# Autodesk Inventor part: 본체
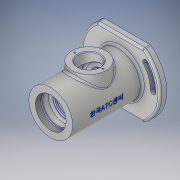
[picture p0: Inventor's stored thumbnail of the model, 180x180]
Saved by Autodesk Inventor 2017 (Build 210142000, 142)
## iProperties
Part Number: 본체
Material: 알루미늄 6061
Document SubType Name: Modeling
Designer: Administrator
Density: 2.7 g/cm^3
Appearance: 알루미늄 - 평지
Mass: 686.655 g
Surface Area: 618.901 cm^2
Volume: 254.317 cm^3
Author: Administrator
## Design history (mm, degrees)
sketch "스케치1"
  geometry: L1 (-33.985, 47)-(33.985, 47); L2 (33.985, 47)-(33.985, -47); L3 (33.985, -47)-(-33.985, -47); L4 (-33.985, -47)-(-33.985, 47); L5 (-33.985, 47)-(33.985, -47); L6 (33.985, 47)-(-33.985, -47); A1 r 58 centre (0, 0) between (-33.985, 47) and (-33.985, -47); A2 r 58 centre (0, 0) between (33.985, 47) and (-33.985, 47); A3 r 58 centre (0, 0) between (-33.985, -47) and (33.985, 47); 1 further point
  constraints: 12 end point, 8 point on circle, 3 centre point, 2 midpoint, 2 parallel, 1 coincident, 1 horizontal, 1 perpendicular
  dimensions: "d0" = 116 diameter of A1; "d1" = 94 distance of L3.end L1.start
extrude "돌출1" new body sketch "스케치1" distance "d2" = 10; taper "d3" = 0 deg
sketch "스케치2"
  geometry: C1 r 36 at (0, 0); 1 further point
  constraints: 1 centre point, 1 coincident
  dimensions: "d4" = 72 diameter of C1
extrude "돌출2" join sketch "스케치2" distance "d5" = 3; taper "d6" = 0 deg
sketch "스케치3"
  geometry: C1 r 32 at (0, 0); 1 further point
  constraints: 1 centre point, 1 coincident
  dimensions: "d7" = 64 diameter of C1
extrude "돌출3" join sketch "스케치3" distance "d8" = 102; taper "d9" = 0 deg
sketch "스케치4"
  geometry: L1 (0, 0)-(48, 0); L2 (0, 0)-(36.77, 30.854); L3 (-48, 0)-(0, 0); L4 (-36.77, -30.854)-(0, 0); C1 r 4 at (-36.77, -30.854); C2 r 4 at (36.77, 30.854); A1 r 48 centre (0, 0) between (48, 0) and (36.77, 30.854); A2 r 48 centre (0, 0) between (48, 0) and (36.77, 30.854); A3 r 48 centre (0, 0) between (-48, 0) and (-36.77, -30.854); 1 further point
  constraints: 8 end point, 8 point on circle, 5 centre point, 3 coincident, 2 concentric, 2 horizontal alignment
  dimensions: "d10" = 96 diameter of A1; "d11" = 40 deg angle of L1 L2; "d13" = 40 deg angle of L4 L3; "d15" = 8 diameter of C1; "d16" = 8 diameter of C2
extrude "돌출4" cut sketch "스케치4" distance "d17" = 10; taper "d18" = 0 deg
sketch "스케치5"
  geometry: L1 (-48, 0)-(48, 0); L2 (-36.77, -30.854)-(36.77, 30.854); C1 r 4 at (-36.77, -30.854) reference; C2 r 4 at (36.77, 30.854) reference; A1 r 48 centre (0, 0) between (-48, 0) and (48, 0); A2 r 48 centre (0, 0) between (48, 0) and (36.77, 30.854); A3 r 52 centre (0, 0) between (52, 0) and (39.834, 33.425); A4 r 44 centre (0, 0) between (44, 0) and (33.706, 28.283); A5 r 4 centre (48, 0) between (44, 0) and (52, 0); A6 r 4 centre (36.77, 30.854) between (39.834, 33.425) and (33.706, 28.283); A7 r 48 centre (0, 0) between (-48, 0) and (-36.77, -30.854); A8 r 52 centre (0, 0) between (-52, 0) and (-39.834, -33.425); A9 r 44 centre (0, 0) between (-44, 0) and (-33.706, -28.283); A10 r 4 centre (-48, 0) between (-44, 0) and (-52, 0); A11 r 4 centre (-36.77, -30.854) between (-39.834, -33.425) and (-33.706, -28.283); 2 further points
  constraints: 22 point on circle, 11 centre point, 8 tangent, 4 end point, 2 concentric, 2 horizontal alignment, 1 coincident, 1 horizontal, 1 midpoint
  dimensions: "d19" = 96 diameter of A1; "d20" = 8 diameter of A5; "d21" = 8 diameter of A10; "d22" = 30.85381 vertical distance of L2.start L1.start
extrude "돌출5" cut sketch "스케치5" distance "d23" = 4.4; taper "d24" = 0 deg
sketch "스케치6" dims "d25" = 96
  geometry: L1 (-36.77, -30.854)-(0, 0); L2 (0, 0)-(36.77, 30.854); L3 (0, 0)-(-48, 0); L4 (0, 0)-(48, 0); C1 r 4 at (-36.77, -30.854) reference; C2 r 4 at (36.77, 30.854) reference; A1 r 4 centre (48, 0) between (44, 0) and (52, 0) reference; A2 r 48 centre (0, 0) between (-48, 0) and (-36.77, -30.854); A3 r 50.25 centre (0, 0) between (-50.25, 0) and (-38.494, -32.3); A4 r 45.75 centre (0, 0) between (-45.75, 0) and (-35.047, -29.408); A5 r 2.25 centre (-48, 0) between (-45.75, 0) and (-50.25, 0); A6 r 2.25 centre (-36.77, -30.854) between (-38.494, -32.3) and (-35.047, -29.408); A7 r 48 centre (0, 0) between (48, 0) and (36.77, 30.854); A8 r 50.25 centre (0, 0) between (50.25, 0) and (38.494, 32.3); A9 r 45.75 centre (0, 0) between (45.75, 0) and (35.047, 29.408); A10 r 2.25 centre (48, 0) between (45.75, 0) and (50.25, 0); A11 r 2.25 centre (36.77, 30.854) between (38.494, 32.3) and (35.047, 29.408); 1 further point
  constraints: 20 point on circle, 10 centre point, 8 end point, 8 tangent, 2 horizontal, 1 coincident, 1 collinear, 1 concentric, 1 horizontal alignment, 3 other
  dimensions: "d26" = 4.5 diameter of A5; "d27" = 4.5 diameter of A10
extrude "돌출6" cut sketch "스케치6" distance "d28" = 10; taper "d29" = 0 deg
sketch "스케치7"
  geometry: L1 (32, 112)-(-32, 112) reference; L2 (0, 112)-(0, -3); L3 (-36, -3)-(36, -3) reference; L4 (0, 112)-(22.5, 112); L5 (22.5, 112)-(22.5, 104); L6 (22.5, 104)-(24, 104); L7 (24, 104)-(24, 101); L8 (24, 101)-(22.5, 101); L9 (22.5, 101)-(22.5, 90); L10 (22.5, 90)-(17.5, 90); L11 (17.5, 90)-(17.5, 88.25); L12 (17.5, 88.25)-(18.5, 88.25); L13 (18.5, 88.25)-(18.5, 86); L14 (18.5, 86)-(17.5, 86); L15 (17.5, 86)-(17.5, 75); L16 (17.5, 75)-(27, 75); L17 (27, 75)-(27, 37); L18 (27, 37)-(17.5, 37); L19 (17.5, 37)-(17.5, 26); L20 (17.5, 26)-(15, 26); L21 (15, 26)-(15, 21); L22 (15, 21)-(11, 21); L23 (11, 21)-(11, 18.3); L24 (11, 18.3)-(15, 18.3); L25 (15, 18.3)-(15, 11); L26 (15, 11)-(20, 11); L27 (20, 11)-(30, -3); 1 further point
  constraints: 50 end point, 19 perpendicular, 4 point on line, 2 midpoint, 1 horizontal, 1 vertical
  dimensions: "d30" = 45 diameter of L5 L2; "d31" = 48 diameter of L7 L2; "d32" = 45 diameter of L9 L2; "d33" = 35 diameter of L11 L2; "d34" = 37 diameter of L13 L2; "d35" = 54 diameter of L17 L2; "d36" = 35 diameter of L19 L2; "d37" = 30 diameter of L21 L2; "d38" = 22 diameter of L23 L2; "d39" = 30 diameter of L25 L2; "d41" = 40 diameter of L26.end L2; "d42" = 60 diameter of L27.end L2; "d43" = 8 distance of L4.end L5.end; "d44" = 3 distance of L6.end L7.end; "d45" = 22 distance between parallel lines of L10 L4; "d47" = 1.75 distance of L10.end L11.end; "d48" = 4 distance between parallel lines of L14 L10; "d49" = 11 distance of L14.end L15.end; "d50" = 38 distance of L16.end L17.end; "d51" = 11 distance of L18.end L19.end; "d52" = 5 distance of L20.end L21.end; "d53" = 14 distance between parallel lines of L3 L26; "d54" = 7.3 distance of L24.end L25.end
revolve "회전1" sketch "스케치7" stored, may be unused: angle "d55" = 90 deg
node "작업 평면1"
sketch "스케치8"
  geometry: L1 (32, 112)-(-32, 112) reference; C1 r 25 at (0, 56); 1 further point
  constraints: 1 centre point, 1 vertical alignment
  dimensions: "d57" = 50 diameter of C1; "d58" = 56 distance from line of C1.centre L1
extrude "돌출7" join sketch "스케치8" stored distance "d59" = 10; taper "d60" = 5 deg
sketch "스케치9"
  geometry: C1 r 25 at (0, 0) reference; C2 r 16 at (0, 0); 1 further point
  constraints: 1 centre point, 1 coincident
  dimensions: "d61" = 32 diameter of C2
extrude "돌출8" cut sketch "스케치9" distance "d62" = 35; taper "d63" = 0 deg
sketch "스케치10"
  geometry: C1 r 25 at (0, 0) reference; A1 r 20.5 centre (0, 0) between (-20.5, 0) and (20.5, 0); 1 further point
  constraints: 2 horizontal alignment, 2 point on circle, 1 centre point, 1 coincident
  dimensions: "d64" = 41 diameter of A1
hole "구멍1" sketch "스케치10" at (-20.5, 0), (20.5, 0) diameter "d65" = 2.459; stored, may be unused: countersink angle "d69" = 90 deg, drill point angle "d71" = 118 deg; dims "d66" = 6, "d67" = 4, "d68" = 2, "d70" = 8
node "작업 평면2"
sketch "스케치11"
  geometry: L1 (47, 0)-(-47, 0) reference; 3 further points
  constraints: 1 midpoint, 1 vertical alignment, 1 other
  dimensions: "d73" = 62 distance from line of L1 point (0, 62)
feature "엠보싱1" sketch "스케치11" dims "d74" = 0.5, "d75" = 0
fillet "모깎기1" dims "d76" = 3
fillet "모깎기2" dims "d77" = 3
fillet "모깎기3" dims "d78" = 3
fillet "모깎기4" dims "d79" = 3
chamfer "모따기1" distance "d80" = 1; stored, may be unused: second distance "d81" = 2, angle "d82" = 45 deg
feature "스레드1" dims "d83" = 10, "d84" = 0
chamfer "모따기2" distance "d85" = 1; stored, may be unused: second distance "d86" = 2, angle "d87" = 30 deg
sketch "스케치12"
  geometry: 1 further point
chamfer "모따기4" distance "d91" = 1; stored, may be unused: second distance "d92" = 2, angle "d93" = 30 deg
chamfer "모따기5" distance "d94" = 1; stored, may be unused: second distance "d95" = 2, angle "d96" = 30 deg
chamfer "모따기6" distance "d97" = 1; stored, may be unused: second distance "d98" = 2, angle "d99" = 30 deg
fillet "모깎기5" dims "d100" = 0.5
fillet "모깎기6" dims "d101" = 0.6
chamfer "모따기7" distance "d102" = 0.7; stored, may be unused: second distance "d103" = 2, angle "d104" = 30 deg
node "솔리드1"
other parameters: "d56" = 38, "d72" = 42
